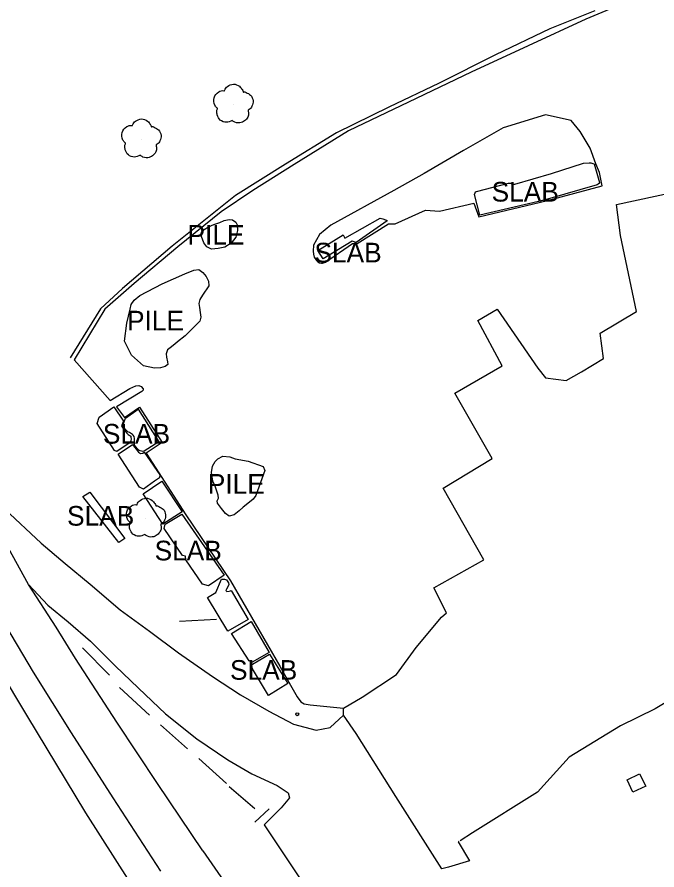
# Model space of a CAD drawing. Extents: x 368532 to 392481, y 10654822 to 10676899.
# Drawn here: x 378795.8 to 378958.5, y 10660531 to 10660747.9 of the extents above; entities that cross this region are included whole.
import ezdxf

# ---------------------------------------------------------------- set-up
doc = ezdxf.new("R2010")
doc.units = 0
for name, color, linetype in [('p_dtm slab', 7, 'Continuous'), ('p_dtm stock pile', 7, 'Continuous'), ('p_railroad rr control', 7, 'Continuous'), ('p_road conc barrier', 7, 'Continuous'), ('p_road dirt road', 7, 'Continuous'), ('p_road general road feature', 7, 'Continuous'), ('p_structure unidentified', 7, 'Continuous'), ('p_veg tree', 7, 'Continuous')]:
    doc.layers.add(name, color=color, linetype=linetype)

msp = doc.modelspace()

# ---------------------------------------------------------------- linework, layer by layer
at = {"layer": 'p_dtm slab'}
for p, q in [((378931.68, 10660708.17), (378939.88, 10660710.73)), ((378939.88, 10660710.73), (378941.29, 10660710.87)), ((378941.29, 10660710.87), (378941.71, 10660710.83)), ((378941.71, 10660710.83), (378942.21, 10660710.7)), ((378942.21, 10660710.7), (378942.58, 10660710.59)), ((378942.58, 10660710.59), (378943.95, 10660705.83)), ((378922.37, 10660705.44), (378931.68, 10660708.17)), ((378912.6, 10660703.59), (378920.82, 10660705.65)), ((378920.82, 10660705.65), (378921.38, 10660705.66)), ((378921.38, 10660705.66), (378921.67, 10660705.54)), ((378921.67, 10660705.54), (378922.13, 10660705.46)), ((378922.13, 10660705.46), (378922.37, 10660705.44)), ((378943.37, 10660705.28), (378930.68, 10660701.62)), ((378943.63, 10660705.4), (378943.37, 10660705.28)), ((378943.96, 10660705.66), (378943.63, 10660705.4)), ((378943.95, 10660705.83), (378943.96, 10660705.66)), ((378948.24, 10660700.28), (378964.91, 10660703.87)), ((378912.16, 10660702.8), (378912.26, 10660703.21)), ((378913.5, 10660697.57), (378912.16, 10660702.8)), ((378912.26, 10660703.21), (378912.38, 10660703.49)), ((378912.38, 10660703.49), (378912.6, 10660703.59)), ((378930.68, 10660701.62), (378928.45, 10660701.05)), ((378928.45, 10660701.05), (378913.5, 10660697.57)), ((378949.24, 10660692.34), (378948.24, 10660700.28)), ((378879.11, 10660691.7), (378888.1, 10660696.79)), ((378889.91, 10660696.1), (378882.05, 10660690.61)), ((378888.1, 10660696.79), (378888.79, 10660696.63)), ((378888.79, 10660696.63), (378889.53, 10660696.39)), ((378889.53, 10660696.39), (378889.86, 10660696.23)), ((378889.86, 10660696.23), (378889.91, 10660696.1)), ((378872.28, 10660688.58), (378878.75, 10660692.51)), ((378881.03, 10660690.91), (378873.67, 10660686.41)), ((378878.75, 10660692.51), (378879.11, 10660691.7)), ((378882.05, 10660690.61), (378881.03, 10660690.91)), ((378953.36, 10660673.03), (378949.24, 10660692.34)), ((378873.67, 10660686.41), (378872.28, 10660688.58)), ((378912.97, 10660670.72), (378917.94, 10660673.6)), ((378917.94, 10660673.6), (378928.25, 10660658.6)), ((378944.08, 10660667.52), (378953.36, 10660673.03)), ((378919.21, 10660659.2), (378912.97, 10660670.72)), ((378944.96, 10660661.11), (378944.08, 10660667.52)), ((378939.38, 10660657.64), (378944.96, 10660661.11)), ((378907.17, 10660652.22), (378919.21, 10660659.2)), ((378928.25, 10660658.6), (378930.2, 10660656.17)), ((378930.2, 10660656.17), (378935.45, 10660655.5)), ((378935.45, 10660655.5), (378939.38, 10660657.64)), ((378916.63, 10660635.62), (378907.17, 10660652.22)), ((378816.63, 10660646.15), (378820.4, 10660648.8)), ((378820.4, 10660648.8), (378822.83, 10660645.09)), ((378823.33, 10660645.87), (378826.56, 10660648.17)), ((378826.56, 10660648.17), (378831.81, 10660639.89)), ((378816.19, 10660644.57), (378816.63, 10660646.15)), ((378822.68, 10660644.05), (378823.33, 10660645.87)), ((378820.56, 10660637.63), (378816.19, 10660644.57)), ((378822.83, 10660645.09), (378822.32, 10660643.98)), ((378822.32, 10660643.98), (378822.82, 10660643.11)), ((378823.28, 10660643.07), (378822.68, 10660644.05)), ((378822.82, 10660643.11), (378823.25, 10660642.56)), ((378823.95, 10660642.44), (378823.28, 10660643.07)), ((378823.25, 10660642.56), (378823.66, 10660642.07)), ((378823.66, 10660642.07), (378824.03, 10660641.71)), ((378824.39, 10660642.27), (378823.95, 10660642.44)), ((378824.03, 10660641.71), (378824.26, 10660641.56)), ((378824.26, 10660641.56), (378824.48, 10660641.48)), ((378824.62, 10660642.12), (378824.39, 10660642.27)), ((378824.48, 10660641.48), (378824.68, 10660641.35)), ((378825.18, 10660641.74), (378824.62, 10660642.12)), ((378824.68, 10660641.35), (378824.73, 10660641)), ((378824.73, 10660641), (378824.76, 10660640.6)), ((378825.35, 10660641.53), (378825.18, 10660641.74)), ((378825.54, 10660641.24), (378825.35, 10660641.53)), ((378825.67, 10660640.74), (378825.54, 10660641.24)), ((378824.52, 10660639.69), (378821.13, 10660637.44)), ((378821.46, 10660636.76), (378825.11, 10660639.21)), ((378824.68, 10660640.14), (378824.52, 10660639.69)), ((378824.76, 10660640.6), (378824.68, 10660640.14)), ((378825.11, 10660639.21), (378826.66, 10660637.26)), ((378825.62, 10660639.28), (378825.63, 10660639.78)), ((378825.73, 10660638.92), (378825.62, 10660639.28)), ((378825.63, 10660639.78), (378825.65, 10660640.29)), ((378825.65, 10660640.29), (378825.67, 10660640.74)), ((378826.01, 10660638.59), (378825.73, 10660638.92)), ((378831.81, 10660639.89), (378828.13, 10660637.49)), ((378821.13, 10660637.44), (378820.56, 10660637.63)), ((378826.92, 10660628.31), (378821.46, 10660636.76)), ((378826.3, 10660638.18), (378826.01, 10660638.59)), ((378826.73, 10660637.75), (378826.3, 10660638.18)), ((378826.66, 10660637.26), (378827.19, 10660636.93)), ((378827.12, 10660637.56), (378826.73, 10660637.75)), ((378827.73, 10660637.42), (378827.12, 10660637.56)), ((378827.19, 10660636.93), (378827.76, 10660636.96)), ((378828.13, 10660637.49), (378827.73, 10660637.42)), ((378827.76, 10660636.96), (378828.12, 10660637.21)), ((378828.12, 10660637.21), (378832.1, 10660631.51)), ((378904.17, 10660628.1), (378916.63, 10660635.62)), ((378832.04, 10660630.68), (378830.72, 10660629.89)), ((378832.1, 10660631.51), (378832.04, 10660630.68)), ((378827.92, 10660627.87), (378826.92, 10660628.31)), ((378827.81, 10660626.61), (378832.61, 10660629.89)), ((378830.72, 10660629.89), (378827.92, 10660627.87)), ((378832.61, 10660629.89), (378837.74, 10660622.06)), ((378914.52, 10660609.83), (378904.17, 10660628.1)), ((378812.5, 10660625.98), (378814.27, 10660627.09)), ((378821.7, 10660614.25), (378812.5, 10660625.98)), ((378814.27, 10660627.09), (378823.15, 10660615.31)), ((378832.82, 10660618.96), (378827.81, 10660626.61)), ((378837.74, 10660622.06), (378832.82, 10660618.96)), ((378833.44, 10660618.9), (378837.71, 10660621.48)), ((378837.71, 10660621.48), (378848.47, 10660605.92)), ((378833.19, 10660617.82), (378833.44, 10660618.9)), ((378837.89, 10660610.98), (378833.19, 10660617.82)), ((378823.15, 10660615.31), (378821.7, 10660614.25)), ((378838.6, 10660610.79), (378837.89, 10660610.98)), ((378838.67, 10660609.88), (378838.6, 10660610.79)), ((378842.97, 10660603.67), (378838.67, 10660609.88)), ((378901.83, 10660602.72), (378914.52, 10660609.83)), ((378848.47, 10660605.92), (378844.44, 10660603.25)), ((378846.32, 10660601.54), (378847.8, 10660604.96)), ((378847.8, 10660604.96), (378848.52, 10660604.98)), ((378848.52, 10660604.98), (378849.08, 10660604.76)), ((378849.08, 10660604.76), (378849.53, 10660604.03)), ((378849.53, 10660604.03), (378849.62, 10660603.54)), ((378844.44, 10660603.25), (378842.97, 10660603.67)), ((378849.02, 10660602.42), (378848.87, 10660602.07)), ((378848.87, 10660602.07), (378849.13, 10660601.78)), ((378849.41, 10660602.99), (378849.02, 10660602.42)), ((378849.13, 10660601.78), (378849.72, 10660601.86)), ((378849.62, 10660603.54), (378849.41, 10660602.99)), ((378849.72, 10660601.86), (378850.07, 10660601.96)), ((378850.07, 10660601.96), (378850.21, 10660602.04)), ((378850.21, 10660602.04), (378854.55, 10660594.67)), ((378905.01, 10660596.39), (378901.83, 10660602.72)), ((378844.25, 10660600.24), (378846.32, 10660601.54)), ((378849.4, 10660591.75), (378844.25, 10660600.24)), ((378897.28, 10660587.55), (378903.77, 10660595.28)), ((378903.77, 10660595.28), (378905.01, 10660596.39)), ((378854.55, 10660594.67), (378849.4, 10660591.75)), ((378850.34, 10660591.11), (378855.3, 10660594.17)), ((378855.3, 10660594.17), (378859.86, 10660586.31)), ((378854.79, 10660584.15), (378850.34, 10660591.11)), ((378892.32, 10660580.7), (378897.28, 10660587.55)), ((378859.86, 10660586.31), (378855.59, 10660583.79)), ((378855.67, 10660583.32), (378859.98, 10660585.86)), ((378859.98, 10660585.86), (378864.69, 10660578.4)), ((378855.59, 10660583.79), (378854.79, 10660584.15)), ((378855.5, 10660582.97), (378855.67, 10660583.32)), ((378855.69, 10660582.13), (378855.5, 10660582.97)), ((378859.7, 10660575.38), (378855.69, 10660582.13)), ((378883.55, 10660574.94), (378892.32, 10660580.7)), ((378864.69, 10660578.4), (378859.7, 10660575.38)), ((378968.98, 10660578.6), (378958.09, 10660571.94)), ((378878.79, 10660572.1), (378883.55, 10660574.94)), ((378878.77, 10660570.31), (378878.79, 10660572.1)), ((378958.09, 10660571.94), (378949.25, 10660567.65)), ((378882.02, 10660565.66), (378878.77, 10660570.31)), ((378949.25, 10660567.65), (378936.25, 10660559.68)), ((378892.13, 10660549.67), (378882.02, 10660565.66)), ((378936.25, 10660559.68), (378928.18, 10660550.74)), ((378928.18, 10660550.74), (378911.61, 10660540.4)), ((378903.83, 10660531.26), (378892.13, 10660549.67)), ((378911.61, 10660540.4), (378908.48, 10660538.41)), ((378908.14, 10660538.2), (378907.98, 10660538.1)), ((378907.98, 10660538.1), (378910.83, 10660533.28)), ((378910.83, 10660533.28), (378905.52, 10660531.65)), ((378905.52, 10660531.65), (378903.83, 10660531.26))]:
    msp.add_line(p, q, dxfattribs=at)
at = {"layer": 'p_dtm stock pile'}
for p, q in [((378844.43, 10660694.57), (378845.79, 10660695.12)), ((378845.79, 10660695.12), (378847.33, 10660695.7)), ((378847.33, 10660695.7), (378848.45, 10660696.15)), ((378848.45, 10660696.15), (378849.76, 10660696.44)), ((378849.76, 10660696.44), (378850.58, 10660696.33)), ((378850.58, 10660696.33), (378851.42, 10660695.77)), ((378851.42, 10660695.77), (378851.76, 10660695.04)), ((378842.63, 10660692.98), (378843.38, 10660693.87)), ((378842.67, 10660692.1), (378842.63, 10660692.98)), ((378843.38, 10660693.87), (378844.43, 10660694.57)), ((378851.87, 10660693.64), (378851.44, 10660691.94)), ((378851.76, 10660695.04), (378851.87, 10660693.64)), ((378843.32, 10660690.52), (378842.67, 10660692.1)), ((378851.44, 10660691.94), (378850.23, 10660690.38)), ((378844.03, 10660689.51), (378843.32, 10660690.52)), ((378845.25, 10660688.9), (378844.03, 10660689.51)), ((378846.95, 10660689.03), (378845.25, 10660688.9)), ((378848.65, 10660689.43), (378846.95, 10660689.03)), ((378850.23, 10660690.38), (378848.65, 10660689.43)), ((378832.71, 10660680.03), (378838.46, 10660682.61)), ((378838.46, 10660682.61), (378840.72, 10660683.52)), ((378840.72, 10660683.52), (378841.97, 10660683.7)), ((378841.97, 10660683.7), (378843.04, 10660682.91)), ((378843.04, 10660682.91), (378843.84, 10660681.94)), ((378827, 10660677.14), (378832.71, 10660680.03)), ((378843.84, 10660681.94), (378844.43, 10660680.73)), ((378844.43, 10660680.73), (378844.57, 10660679.54)), ((378844.57, 10660679.54), (378842.92, 10660677.2)), ((378824.84, 10660674.8), (378825.57, 10660675.93)), ((378825.57, 10660675.93), (378827, 10660677.14)), ((378842.27, 10660676.11), (378841.99, 10660675.07)), ((378842.92, 10660677.2), (378842.27, 10660676.11)), ((378823.69, 10660670.02), (378824.57, 10660673.61)), ((378824.57, 10660673.61), (378824.84, 10660674.8)), ((378841.99, 10660675.07), (378842.19, 10660674.04)), ((378842.19, 10660674.04), (378842.37, 10660672.78)), ((378842.55, 10660671.62), (378842.28, 10660670.58)), ((378842.37, 10660672.78), (378842.55, 10660671.62)), ((378823.13, 10660665.48), (378823.69, 10660670.02)), ((378842.28, 10660670.58), (378840.2, 10660668.51)), ((378838.55, 10660666.88), (378836.6, 10660665.3)), ((378840.2, 10660668.51), (378838.55, 10660666.88)), ((378824.85, 10660661.93), (378823.13, 10660665.48)), ((378835.89, 10660664.7), (378834.74, 10660663.82)), ((378836.6, 10660665.3), (378835.89, 10660664.7)), ((378834.06, 10660663.24), (378833.71, 10660662.29)), ((378834.74, 10660663.82), (378834.06, 10660663.24)), ((378827.9, 10660659.24), (378824.85, 10660661.93)), ((378833.71, 10660662.29), (378833.75, 10660661.45)), ((378833.75, 10660661.45), (378834.08, 10660660.22)), ((378830.71, 10660658.59), (378827.9, 10660659.24)), ((378832.22, 10660658.66), (378830.71, 10660658.59)), ((378833.48, 10660659.08), (378832.22, 10660658.66)), ((378834.09, 10660659.57), (378833.48, 10660659.08)), ((378834.08, 10660660.22), (378834.09, 10660659.57)), ((378845.52, 10660633.65), (378846.17, 10660634.86)), ((378846.17, 10660634.86), (378846.87, 10660635.57)), ((378846.87, 10660635.57), (378848.09, 10660636.21)), ((378848.09, 10660636.21), (378849.89, 10660636.06)), ((378849.89, 10660636.06), (378851.22, 10660635.53)), ((378851.22, 10660635.53), (378854.53, 10660634.92)), ((378854.53, 10660634.92), (378858.34, 10660633.59)), ((378845.27, 10660632.1), (378845.52, 10660633.65)), ((378858.8, 10660632.55), (378856.48, 10660626.25)), ((378858.34, 10660633.59), (378858.8, 10660632.55)), ((378845.55, 10660629.88), (378845.27, 10660632.1)), ((378846.24, 10660628.3), (378845.55, 10660629.88)), ((378846.93, 10660626.27), (378846.24, 10660628.3)), ((378847.01, 10660625.55), (378846.93, 10660626.27)), ((378856.48, 10660626.25), (378855.87, 10660625.3)), ((378846.7, 10660624.88), (378847.01, 10660625.55)), ((378846.8, 10660624.26), (378846.7, 10660624.88)), ((378847.76, 10660622.92), (378846.8, 10660624.26)), ((378854.48, 10660624.19), (378853.29, 10660623.24)), ((378855.87, 10660625.3), (378854.48, 10660624.19)), ((378848.79, 10660621.64), (378847.76, 10660622.92)), ((378849.76, 10660620.94), (378848.79, 10660621.64)), ((378850.97, 10660621.34), (378849.76, 10660620.94)), ((378852.3, 10660622.3), (378850.97, 10660621.34)), ((378853.29, 10660623.24), (378852.3, 10660622.3))]:
    msp.add_line(p, q, dxfattribs=at)
at = {"layer": 'p_railroad rr control'}
msp.add_lwpolyline([(378591.5, 10660992.56), (378612.01, 10660944.51), (378635.21, 10660890.62), (378654.82, 10660845.94), (378673.49, 10660804.23), (378692.1, 10660765.2), (378705.02, 10660738.76), (378720.05, 10660708.54), (378736.93, 10660676.64), (378754.69, 10660644.59), (378770.4, 10660617.11), (378784.2, 10660593.58), (378798.17, 10660570.34), (378813.16, 10660545.51), (378828.14, 10660522.13)], dxfattribs=at)
at = {"layer": 'p_road conc barrier'}
for p, q in [((378942.74, 10660749.52), (378931.29, 10660744.91)), ((378931.29, 10660744.91), (378917.49, 10660738.35)), ((378917.49, 10660738.35), (378903.16, 10660731.1)), ((378903.16, 10660731.1), (378890.35, 10660725)), ((378890.35, 10660725), (378877, 10660718.49)), ((378877, 10660718.49), (378864.04, 10660710.47)), ((378864.04, 10660710.47), (378851.33, 10660702.55)), ((378851.33, 10660702.55), (378835.19, 10660689.61)), ((378835.19, 10660689.61), (378822.58, 10660678.91)), ((378822.58, 10660678.91), (378817.01, 10660673.74)), ((378817.01, 10660673.74), (378809.27, 10660661.22)), ((378846.48, 10660594.64), (378837.09, 10660594.15)), ((378812.4, 10660587.44), (378819.25, 10660580.49)), ((378821.86, 10660577.38), (378829.44, 10660570.34)), ((378832.26, 10660567.9), (378839.16, 10660561.78)), ((378842.04, 10660559.33), (378849.02, 10660553)), ((378849.71, 10660552.18), (378856.27, 10660546.63)), ((378856.24, 10660543.13), (378859.91, 10660546.53))]:
    msp.add_line(p, q, dxfattribs=at)
at = {"layer": 'p_road dirt road'}
for p, q in [((378798.66, 10660603.6), (378789.39, 10660620.35)), ((378805.68, 10660592.7), (378798.66, 10660603.6)), ((378799.93, 10660581.29), (378791.59, 10660595.43)), ((378810.63, 10660584.74), (378805.68, 10660592.7)), ((378821.13, 10660568.6), (378810.63, 10660584.74)), ((378809.61, 10660565.87), (378799.93, 10660581.29)), ((378831.54, 10660552.92), (378821.13, 10660568.6)), ((378820.22, 10660549.3), (378809.61, 10660565.87)), ((378843.06, 10660535.82), (378831.54, 10660552.92)), ((378832.35, 10660530.68), (378820.22, 10660549.3)), ((378843.06, 10660535.82), (378860.05, 10660511.41))]:
    msp.add_line(p, q, dxfattribs=at)
at = {"layer": 'p_road general road feature'}
for p, q in [((378949.62, 10660751.22), (378940.43, 10660747.43)), ((378940.43, 10660747.43), (378925.78, 10660740.59)), ((378925.78, 10660740.59), (378911.25, 10660733.95)), ((378911.25, 10660733.95), (378895.35, 10660726.31)), ((378895.35, 10660726.31), (378880.06, 10660718.97)), ((378930.17, 10660723.06), (378919.46, 10660719.79)), ((378936.76, 10660721.6), (378930.17, 10660723.06)), ((378939.01, 10660718.84), (378936.76, 10660721.6)), ((378880.06, 10660718.97), (378866.29, 10660710.44)), ((378919.46, 10660719.79), (378909.35, 10660713.98)), ((378941.57, 10660714.57), (378939.01, 10660718.84)), ((378909.35, 10660713.98), (378899.35, 10660708.17)), ((378943.03, 10660710.63), (378941.57, 10660714.57)), ((378866.29, 10660710.44), (378855.74, 10660703.81)), ((378943.95, 10660708.42), (378943.03, 10660710.63)), ((378899.35, 10660708.17), (378891.65, 10660703.85)), ((378944.6, 10660704.97), (378943.95, 10660708.42)), ((378855.74, 10660703.81), (378847.67, 10660698.37)), ((378891.65, 10660703.85), (378875.61, 10660694.95)), ((378930.73, 10660701.24), (378944.6, 10660704.97)), ((378903.25, 10660698.55), (378911.98, 10660700.61)), ((378911.98, 10660700.61), (378913.21, 10660697.15)), ((378913.21, 10660697.15), (378930.73, 10660701.24)), ((378847.67, 10660698.37), (378836.71, 10660689.5)), ((378891.97, 10660695.34), (378899.67, 10660698.78)), ((378899.67, 10660698.78), (378903.25, 10660698.55)), ((378882.3, 10660690.32), (378890.22, 10660695.31)), ((378890.22, 10660695.31), (378891.97, 10660695.34)), ((378875.61, 10660694.95), (378872.69, 10660692.6)), ((378872.69, 10660692.6), (378871.21, 10660689.92)), ((378836.71, 10660689.5), (378825.6, 10660680.16)), ((378871.21, 10660689.92), (378871.1, 10660688.41)), ((378874.2, 10660685.59), (378881.08, 10660690.31)), ((378881.08, 10660690.31), (378882.3, 10660690.32)), ((378871.1, 10660688.41), (378871.14, 10660687.59)), ((378871.14, 10660687.59), (378871.36, 10660686.89)), ((378871.36, 10660686.89), (378871.9, 10660686.02)), ((378871.9, 10660686.02), (378872.28, 10660685.65)), ((378872.28, 10660685.65), (378872.7, 10660685.42)), ((378872.7, 10660685.42), (378873.18, 10660685.33)), ((378873.18, 10660685.33), (378873.5, 10660685.33)), ((378873.5, 10660685.33), (378874.2, 10660685.59)), ((378825.6, 10660680.16), (378818.09, 10660673.59)), ((378818.09, 10660673.59), (378810.28, 10660660.74)), ((378810.28, 10660660.74), (378819.44, 10660650.41)), ((378824.44, 10660653.48), (378826.02, 10660654.12)), ((378826.02, 10660654.12), (378826.79, 10660654.21)), ((378826.79, 10660654.21), (378827.38, 10660653.99)), ((378827.38, 10660653.99), (378827.83, 10660653.36)), ((378819.44, 10660650.41), (378824.44, 10660653.48)), ((378827.53, 10660652.65), (378821.11, 10660648.74)), ((378827.82, 10660653), (378827.53, 10660652.65)), ((378827.83, 10660653.36), (378827.82, 10660653)), ((378821.11, 10660648.74), (378823.07, 10660646.05)), ((378823.07, 10660646.05), (378826.93, 10660648.66)), ((378826.93, 10660648.66), (378832.66, 10660639.68)), ((378832.66, 10660639.68), (378828.65, 10660637.03)), ((378828.65, 10660637.03), (378838.71, 10660621.31)), ((378792.68, 10660622.75), (378801.89, 10660614.13)), ((378838.71, 10660621.31), (378850.08, 10660604.48)), ((378801.89, 10660614.13), (378808.02, 10660608.91)), ((378808.02, 10660608.91), (378814.38, 10660603.63)), ((378850.08, 10660604.48), (378862.64, 10660582.77)), ((378798.66, 10660603.6), (378803.64, 10660598.31)), ((378814.38, 10660603.63), (378822.04, 10660597.14)), ((378803.64, 10660598.31), (378808.74, 10660594.05)), ((378822.04, 10660597.14), (378829.46, 10660591.75)), ((378808.74, 10660594.05), (378814.48, 10660589.14)), ((378829.46, 10660591.75), (378836.8, 10660586.16)), ((378814.48, 10660589.14), (378820.75, 10660582.93)), ((378836.8, 10660586.16), (378845.48, 10660580.2)), ((378820.75, 10660582.93), (378826.68, 10660577.23)), ((378862.64, 10660582.77), (378865.31, 10660577.97)), ((378845.48, 10660580.2), (378852.62, 10660575.55)), ((378865.31, 10660577.97), (378867.01, 10660575.01)), ((378826.68, 10660577.23), (378833.57, 10660570.71)), ((378852.62, 10660575.55), (378859.83, 10660571.36)), ((378867.01, 10660575.01), (378867.95, 10660573.76)), ((378867.95, 10660573.76), (378868.8, 10660573.23)), ((378868.8, 10660573.23), (378870.31, 10660573.01)), ((378870.31, 10660573.01), (378878.79, 10660572.1)), ((378833.57, 10660570.71), (378841.48, 10660564.28)), ((378859.83, 10660571.36), (378866.13, 10660568.02)), ((378875.39, 10660567.17), (378878.77, 10660570.31)), ((378866.13, 10660568.02), (378871.86, 10660566.5)), ((378871.86, 10660566.5), (378875.39, 10660567.17)), ((378841.48, 10660564.28), (378849.36, 10660559.02)), ((378849.36, 10660559.02), (378855.53, 10660555.38)), ((378855.53, 10660555.38), (378861.94, 10660552.41)), ((378861.94, 10660552.41), (378864.71, 10660550.55)), ((378864.71, 10660550.55), (378865.05, 10660549.3)), ((378865.05, 10660549.3), (378862.99, 10660546.79)), ((378862.99, 10660546.79), (378858.62, 10660542.44)), ((378858.62, 10660542.44), (378876.88, 10660515.18))]:
    msp.add_line(p, q, dxfattribs=at)
at = {"layer": 'p_structure unidentified'}
for p, q in [((378950.97, 10660553.93), (378954.11, 10660555.42)), ((378954.11, 10660555.42), (378955.71, 10660552.27)), ((378952.41, 10660550.79), (378950.97, 10660553.93)), ((378955.71, 10660552.27), (378952.41, 10660550.79))]:
    msp.add_line(p, q, dxfattribs=at)
msp.add_circle((378867.05, 10660570.59), 0.375, dxfattribs=at)
at = {"layer": 'p_veg tree'}
for p, q in [((378850.76, 10660725.76), (378850.76, 10660725.76)), ((378827.37, 10660716.91), (378827.37, 10660716.91)), ((378828.54, 10660620.44), (378828.54, 10660620.44))]:
    msp.add_line(p, q, dxfattribs=at)
for points in [[(378850.48, 10660721.6), (378848.99, 10660721.17), (378847.48, 10660721.74), (378846.7, 10660723.02), (378846.57, 10660723.87), (378846.72, 10660724.55), (378846.79, 10660724.68), (378846.71, 10660724.76), (378846.1, 10660725.5), (378845.88, 10660727.41), (378847.1, 10660728.9), (378848.37, 10660729.18), (378848.51, 10660729.18), (378848.56, 10660729.29), (378849.28, 10660730.27), (378850.79, 10660730.85), (378852.37, 10660730.31), (378853.06, 10660729.47), (378853.27, 10660728.96), (378853.29, 10660728.85), (378853.39, 10660728.88), (378854.05, 10660728.76), (378855.13, 10660728.07), (378855.79, 10660726.65), (378855.53, 10660725.28), (378854.8, 10660724.41), (378854.57, 10660724.28), (378854.53, 10660724.22), (378854.54, 10660724.15), (378854.62, 10660723.71), (378854.56, 10660722.73), (378853.88, 10660721.73), (378852.8, 10660721.07), (378851.2, 10660721.17), (378850.46, 10660721.6)], [(378827.08, 10660712.76), (378825.59, 10660712.32), (378824.08, 10660712.89), (378823.3, 10660714.18), (378823.17, 10660715.02), (378823.33, 10660715.7), (378823.39, 10660715.84), (378823.31, 10660715.91), (378822.7, 10660716.65), (378822.49, 10660718.57), (378823.7, 10660720.05), (378824.97, 10660720.34), (378825.11, 10660720.33), (378825.16, 10660720.45), (378825.88, 10660721.43), (378827.39, 10660722.01), (378828.97, 10660721.46), (378829.66, 10660720.62), (378829.87, 10660720.11), (378829.89, 10660720), (378829.99, 10660720.04), (378830.65, 10660719.92), (378831.73, 10660719.23), (378832.39, 10660717.8), (378832.13, 10660716.43), (378831.4, 10660715.57), (378831.17, 10660715.43), (378831.13, 10660715.37), (378831.14, 10660715.31), (378831.22, 10660714.86), (378831.16, 10660713.89), (378830.48, 10660712.88), (378829.4, 10660712.23), (378827.8, 10660712.33), (378827.06, 10660712.76)], [(378828.25, 10660616.28), (378826.76, 10660615.85), (378825.25, 10660616.42), (378824.47, 10660617.7), (378824.34, 10660618.55), (378824.5, 10660619.23), (378824.56, 10660619.37), (378824.48, 10660619.44), (378823.87, 10660620.18), (378823.66, 10660622.1), (378824.87, 10660623.58), (378826.14, 10660623.87), (378826.29, 10660623.86), (378826.33, 10660623.97), (378827.05, 10660624.95), (378828.56, 10660625.53), (378830.14, 10660624.99), (378830.83, 10660624.15), (378831.04, 10660623.64), (378831.06, 10660623.53), (378831.16, 10660623.56), (378831.82, 10660623.44), (378832.9, 10660622.75), (378833.56, 10660621.33), (378833.31, 10660619.96), (378832.57, 10660619.09), (378832.34, 10660618.96), (378832.31, 10660618.9), (378832.31, 10660618.84), (378832.39, 10660618.39), (378832.33, 10660617.41), (378831.65, 10660616.41), (378830.57, 10660615.75), (378828.97, 10660615.85), (378828.23, 10660616.29)]]:
    msp.add_spline(points, degree=3, dxfattribs=at)

# ---------------------------------------------------------------- texts
at = {"layer": 'p_dtm slab'}
for p in [(378914.63, 10660700.99), (378869.56, 10660685.51), (378815.75, 10660639.42), (378806.63, 10660618.55), (378828.9, 10660609.71), (378848.09, 10660579.35)]:
    msp.add_text(' SLAB', height=5, dxfattribs=at).set_placement(p)
at = {"layer": 'p_dtm stock pile'}
for p in [(378837.28, 10660690.03), (378821.89, 10660668.2), (378842.43, 10660626.67)]:
    msp.add_text(' PILE', height=5, dxfattribs=at).set_placement(p)

doc.saveas('drawing.dxf')
